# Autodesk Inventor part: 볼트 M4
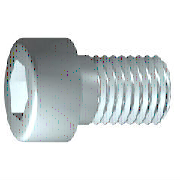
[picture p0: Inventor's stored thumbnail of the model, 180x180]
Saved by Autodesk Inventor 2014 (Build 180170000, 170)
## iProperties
IsCustomPart: 0
Created: 2018-09
Part Number: 볼트 M4
Material: 스테인리스강
Description: 6각머리 태핑 나사
Document SubType Name: Modeling
Standard: KS B 1003
Standards Organization: KS
Language: ko-KR
Size Designation: M 4 x 10
Categories: <MemberInstance><Categories><Category DisplayName="조임쇠" InternalName="e4da775c-781d-43d5-af7c-5136215cf5a6" Mnemonic="FSTN"><Category DisplayName="볼트" InternalN
Density: 8.08 g/cm^3
Appearance: 반광택
Mass: 2.09412 g
Surface Area: 3.0572 cm^2
Volume: 0.259174 cm^3
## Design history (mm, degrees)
sketch "스케치1"
  geometry: L1 (-1, 0)-(10, 0); L2 (10, 0)-(10, 2); L3 (10, 2)-(1.75, 2); L4 (1.75, 2)-(1.32, 2); L5 (1.32, 2)-(0, 2); L6 (0, 2)-(0, 3.5); L7 (0, 3.5)-(-4, 3.5); L8 (-4, 3.5)-(-4, 1.732); L9 (-4, 1.732)-(-2, 1.732); L10 (-2, 1.732)-(-1, 0); L11 (-6.8, 0)-(12.8, 0) reference; L12 (0, -0.7)-(0, 4.2) reference; L13 (1.75, 2)-(0, 2)
  constraints: 22 end point, 6 parallel, 2 collinear, 2 perpendicular, 1 horizontal, 1 point on line
  dimensions: "d1" = 8.25 distance from line of L3.end L2 (= GEL); "d2" = 0.42952 distance of L4.end L3.end (computed from GAL); "d3" = 4 distance between parallel lines of L8 L6 (= KOH); "d4" = 2 distance of L8.end L9.end (= INTI); "d5" = 60 deg angle of L10 L1; "d6" = 4 diameter of L3 L1 (= GD); "d7" = 4 diameter of L5 L1 (= BDM); "d8" = 3.4641 diameter of L9 L1 (= 1.1547 x SW); "d9" = 7 diameter of L7 L1 (= KOD); "d26" = 10 distance between parallel lines of L12 L2 (= NLG)
revolve "본체" sketch "스케치1" stored, may be unused: angle "d10" = 90 deg
sketch "스케치2"
  geometry: L1 (0, -4.9)-(0, 4.9) reference; L2 (-4.9, 0)-(4.9, 0) reference; L3 (1.732, 0)-(0.866, -1.5); L4 (0.866, -1.5)-(-0.866, -1.5); L5 (-0.866, -1.5)-(-1.732, 0); L6 (-1.732, 0)-(-0.866, 1.5); L7 (-0.866, 1.5)-(0.866, 1.5); L8 (0.866, 1.5)-(1.732, 0); 2 further points
  constraints: 12 end point, 1 coincident, 1 horizontal alignment, 1 point on line, 12 other
extrude "슬롯" join sketch "스케치2" stored distance "d11" = 10; taper "d12" = 0 deg
workplane "Work Plane1"
fillet "Fillet2" dims "d30" = 0.1 (= R)
body "Solid1"
fillet "모깎기1" dims "d17" = 0.4 (= RR)
feature "스레드" dims "d13" = 8.25 (= GEL), "d14" = 0
chamfer "모따기1" distance "d15" = 0.42941 (= -0.5 x SPD + 0.5 x GD); stored, may be unused: second distance "d16" = 0.42941 (= GUL), angle "d27" = 45 deg
other parameters: "GD" = 4 (= NND) [user parameter; used in 2 equation terms], "NLG" = 10 [user parameter; used in 1 equation term], "GEL" = 8.25 [user parameter; used in 2 equation terms], "KOD" = 7 [user parameter; used in 1 equation term], "KOH" = 4 [user parameter; used in 1 equation term], "INTI" = 2 [user parameter; used in 1 equation term], "GAL" = 0.42941 (= 0.61345 x PTC) [user parameter; used in 1 equation term], "GUL" = 0.42941 (= 0.61345 x PTC) [user parameter; used in 1 equation term], "BDM" = 4 (= NND) [user parameter; used in 1 equation term], "SW" = 3 [user parameter; used in 2 equation terms], "RR" = 0.4 [user parameter; used in 1 equation term], "SPD" = 3.14117 (= NND - 1.2269 x PTC) [user parameter; used in 1 equation term], "d19" = 0, "d28" = 0, "d29" = 0, "R" = 0.1 [user parameter; used in 1 equation term], "PHH" = 0.2 [user parameter], "GD1" = 3.14117 (= THREADDIA - 1.2269 x PTC) [user parameter], "THREADDIA" = 4 [user parameter; used in 1 equation term], "FAWI" = 45 deg [user parameter], "TPU" = 14.28571 (computed from PTC) [user parameter], "PTC" = 0.7 [user parameter; used in 5 equation terms], "NND" = 4 [user parameter; used in 3 equation terms], "TOA" = 30 deg [user parameter], "E0" = 3.465 (= 1.155 x SW) [user parameter]
